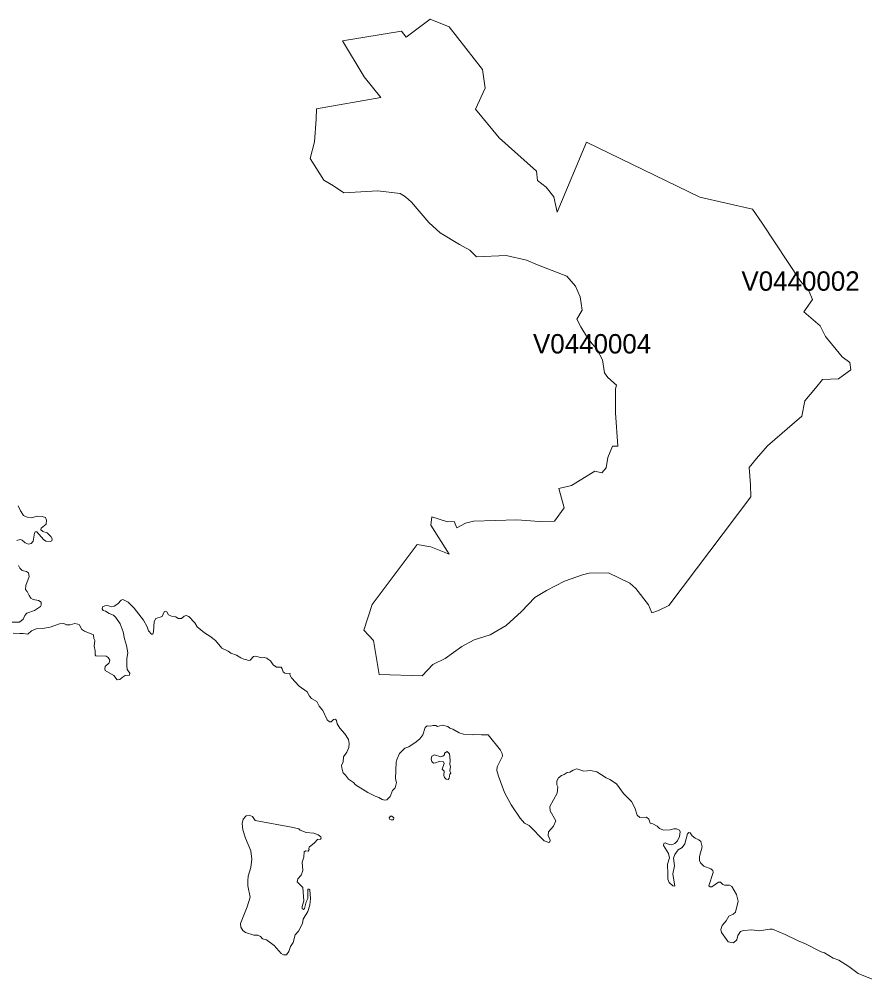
# Model space of a CAD drawing. Extents: x 369010 to 735936, y 6377141 to 6616555.
# Drawn here: x 376246 to 380608, y 6456886 to 6461842 of the extents above; entities that cross this region are included whole.
import ezdxf
from ezdxf.enums import TextEntityAlignment as Align

# ---------------------------------------------------------------- set-up
doc = ezdxf.new("R2010")
doc.units = 0
doc.header["$LTSCALE"] = 40
doc.layers.add('3', color=7, linetype='Continuous', lineweight=13)
doc.layers.add('4', color=7, linetype='Continuous')

msp = doc.modelspace()

# ---------------------------------------------------------------- linework, layer by layer
at = {"layer": '3'}
for points in [[(379071.69, 6460516.27), (378919.43, 6460575.36), (378862.99, 6460598.53), (378757.9, 6460623.52), (378605.63, 6460615.58), (378571.37, 6460649.67), (378517.58, 6460678.63), (378417.78, 6460740.37), (378358.7, 6460792.83), (378269.49, 6460897.93), (378239.21, 6460925.57), (378210.41, 6460942.61), (378096.21, 6460957.18), (377920.28, 6460945.26), (377867.82, 6460982.33), (377816.67, 6461011.3), (377747, 6461123.01), (377768.68, 6461208.91), (377777.78, 6461325.75), (377780.43, 6461379.71), (378111.27, 6461437.47), (378024.88, 6461544.22), (377914.16, 6461730.08), (378218.85, 6461780.06), (378242.35, 6461748.45), (378366.64, 6461841.8), (378463.8, 6461802.41), (378635.75, 6461581.79), (378650.48, 6461486.13), (378599.18, 6461377.23), (378721.32, 6461229.93), (378914.96, 6461057.47), (378920.26, 6461008.81), (378964.94, 6460974.56), (379004.33, 6460926.06), (379021.38, 6460845.79), (379172.98, 6461207.25), (379756.22, 6460924.41), (380029.3, 6460862.51), (380079.11, 6460789.03), (380276.39, 6460490.79), (380319.76, 6460440.97), (380338.13, 6460394.96), (380293.44, 6460331.9), (380377.52, 6460259.58), (380405.16, 6460204.47), (380490.39, 6460099.04), (380531.11, 6460071.4), (380536.4, 6460032.01), (380472.02, 6459986), (380389.27, 6459983.35), (380353.85, 6459937.51), (380298.74, 6459873.13), (380283.01, 6459794.18), (380106.09, 6459640.26), (380049.65, 6459574.56), (380011.59, 6459528.55), (380018.21, 6459439.17), (380020.36, 6459377.77), (379596.5, 6458817.54), (379544.04, 6458791.23), (379509.95, 6458779.48), (379491.57, 6458820.19), (379427.19, 6458904.27), (379395.58, 6458931.91), (379285.36, 6458985.69), (379185.56, 6458984.37), (379151.13, 6458975.93), (379059.11, 6458941.67), (378965.93, 6458894.34), (378905.53, 6458858.92), (378837.34, 6458785.43), (378757.23, 6458714.43), (378675.81, 6458665.77), (378593.22, 6458640.12), (378530.16, 6458606.03), (378443.44, 6458544.29), (378380.38, 6458512.68), (378325.27, 6458453.6), (378102.17, 6458460.22), (378072.87, 6458636.31), (378024.38, 6458688.78), (378066.25, 6458821.51), (378298.13, 6459131.01), (378368.96, 6459119.26), (378463.63, 6459082.35), (378368.96, 6459230.81), (378374.26, 6459274.17), (378455.69, 6459249.18), (378489.78, 6459250.5), (378503.02, 6459217.73), (378547.54, 6459241.4), (378589.58, 6459251.82), (378813.17, 6459259.11), (378930.02, 6459249.84), (379008.14, 6459252.82), (379056.63, 6459321.17), (379030.32, 6459420.97), (379094.7, 6459435.37), (379215.51, 6459510.34)], [(379071.69, 6460516.27), (379115.05, 6460464.97), (379139.88, 6460409.86), (379149.15, 6460340.18), (379122.83, 6460294.17), (379143.52, 6460255.27), (379177.78, 6460197.51), (379201.28, 6460167.23), (379224.95, 6460139.59), (379255.24, 6460084.47), (379264.34, 6460017.45), (379282.71, 6459993.78), (379327.39, 6459954.39), (379322.1, 6459934.69), (379321.44, 6459811.72), (379333.35, 6459638.28), (379305.71, 6459639.6), (379282.38, 6459580.02), (379274.6, 6459527.39), (379250.93, 6459501.07), (379215.51, 6459510.34), (379094.7, 6459435.37), (379030.32, 6459420.97), (379056.63, 6459321.17), (379008.14, 6459252.82), (378930.02, 6459249.84), (378813.17, 6459259.11), (378589.58, 6459251.82), (378547.54, 6459241.4), (378503.02, 6459217.73), (378489.78, 6459250.5), (378455.69, 6459249.18), (378374.26, 6459274.17), (378368.96, 6459230.81), (378463.63, 6459082.35), (378368.96, 6459119.26), (378298.13, 6459131.01), (378066.25, 6458821.51), (378024.38, 6458688.78), (378072.87, 6458636.31), (378102.17, 6458460.22), (378325.27, 6458453.6), (378380.38, 6458512.68), (378443.44, 6458544.29), (378530.16, 6458606.03), (378593.22, 6458640.12), (378675.81, 6458665.77), (378757.23, 6458714.43), (378837.34, 6458785.43), (378905.53, 6458858.92), (378965.93, 6458894.34), (379059.11, 6458941.67), (379151.13, 6458975.93), (379185.56, 6458984.37), (379285.36, 6458985.69), (379395.58, 6458931.91), (379427.19, 6458904.27), (379491.57, 6458820.19), (379509.95, 6458779.48), (379544.04, 6458791.23), (379596.5, 6458817.54), (380020.36, 6459377.77), (380018.21, 6459439.17), (380011.59, 6459528.55), (380049.65, 6459574.56), (380106.09, 6459640.26), (380283.01, 6459794.18), (380298.74, 6459873.13), (380353.85, 6459937.51), (380389.27, 6459983.35), (380472.02, 6459986), (380536.4, 6460032.01), (380531.11, 6460071.4), (380490.39, 6460099.04), (380405.16, 6460204.47), (380377.52, 6460259.58), (380293.44, 6460331.9), (380338.13, 6460394.96), (380319.76, 6460440.97), (380276.39, 6460490.79), (380079.11, 6460789.03), (380029.3, 6460862.51), (379756.22, 6460924.41), (379172.98, 6461207.25), (379021.38, 6460845.79), (379004.33, 6460926.06), (378964.94, 6460974.56), (378920.26, 6461008.81), (378914.96, 6461057.47), (378721.32, 6461229.93), (378599.18, 6461377.23), (378650.48, 6461486.13), (378635.75, 6461581.79), (378463.8, 6461802.41), (378366.64, 6461841.8), (378242.35, 6461748.45), (378218.85, 6461780.06), (377914.16, 6461730.08), (378024.88, 6461544.22), (378111.27, 6461437.47)], [(378111.27, 6461437.47), (377780.43, 6461379.71), (377777.78, 6461325.75), (377768.68, 6461208.91), (377747, 6461123.01), (377816.67, 6461011.3), (377867.82, 6460982.33), (377920.28, 6460945.26), (378096.21, 6460957.18), (378210.41, 6460942.61), (378239.21, 6460925.57), (378269.49, 6460897.93), (378358.7, 6460792.83), (378417.78, 6460740.37), (378517.58, 6460678.63), (378571.37, 6460649.67), (378605.63, 6460615.58), (378757.9, 6460623.52), (378862.99, 6460598.53), (378919.43, 6460575.36), (379071.69, 6460516.27)], [(379215.51, 6459510.34), (379250.93, 6459501.07), (379274.6, 6459527.39), (379282.38, 6459580.02), (379305.71, 6459639.6), (379333.35, 6459638.28), (379321.44, 6459811.72), (379322.1, 6459934.69), (379327.39, 6459954.39), (379282.71, 6459993.78), (379264.34, 6460017.45), (379255.24, 6460084.47), (379224.95, 6460139.59), (379201.28, 6460167.23), (379177.78, 6460197.51), (379143.52, 6460255.27), (379122.83, 6460294.17), (379149.15, 6460340.18), (379139.88, 6460409.86), (379115.05, 6460464.97), (379071.69, 6460516.27)], [(376241.57, 6459331.93), (376252.99, 6459305.78), (376268.72, 6459281.45), (376288.08, 6459273.01), (376310.42, 6459269.2), (376339.39, 6459277.64), (376364.21, 6459275.33), (376381.26, 6459270.53), (376387.88, 6459256.79), (376385.56, 6459235.94), (376359.91, 6459215.41), (376358.42, 6459206.81), (376368.85, 6459199.19), (376390.69, 6459192.08), (376409.23, 6459173.54), (376415.52, 6459160.8), (376415.02, 6459151.2), (376405.42, 6459147.06), (376384.07, 6459149.38), (376371.33, 6459156.99), (376337.57, 6459196.88), (376329.46, 6459197.37), (376324.66, 6459189.26), (376318.53, 6459148.88), (376307.61, 6459136.96), (376294.7, 6459132.66), (376277.16, 6459140.27), (376261.43, 6459153.68), (376251.5, 6459156.99), (376233.46, 6459152.19)], [(376242.73, 6459023.43), (376250.34, 6459008.7), (376262.26, 6458997.78), (376284.6, 6458992.98), (376294.04, 6458984.87), (376297.18, 6458965.83), (376279.64, 6458919.33), (376278.65, 6458899.8), (376288.08, 6458889.87), (376297.18, 6458868.02), (376305.62, 6458854.61), (376317.54, 6458847.99), (376346.17, 6458842.37), (376358.92, 6458833.26), (376359.41, 6458819.03), (376355.61, 6458810.92), (376325.15, 6458791.89), (376285.27, 6458777.16), (376275.34, 6458764.91), (376266.73, 6458746.87), (376247.7, 6458731.15), (376206.82, 6458730.16)], [(376508.53, 6458717.25), (376533.36, 6458723.54), (376548.58, 6458720.72), (376558.02, 6458717.74), (376567.95, 6458694.57), (376583.17, 6458683.98), (376630.34, 6458665.94), (376631.67, 6458646.08), (376636.96, 6458635.98), (376632.66, 6458606.52), (376638.29, 6458583.35), (376637.79, 6458561.84), (376642.09, 6458556.71), (376694.39, 6458554.72), (376704.82, 6458548.6), (376712.93, 6458534.86), (376710.61, 6458520.46), (376689.26, 6458502.42), (376687.77, 6458490.17), (376690.42, 6458481.73), (376735.11, 6458455.58), (376751.49, 6458433.41), (376765.56, 6458434.4), (376777.64, 6458445.49), (376792.2, 6458455.25), (376815.38, 6458458.23), (376817.03, 6458467.34), (376803.96, 6458485.87), (376801.14, 6458505.4), (376801.14, 6458543.8), (376806.27, 6458573.26), (376800.48, 6458610.33), (376789.06, 6458644.09), (376782.77, 6458681.66), (376767.54, 6458722.54), (376745.2, 6458755.31), (376731.96, 6458767.23), (376710.11, 6458775.34), (376691.58, 6458787.09), (376679.17, 6458791.89), (376674.03, 6458799.01), (376675.86, 6458809.43), (376688.76, 6458815.72), (376703.49, 6458816.22), (376721.04, 6458809.93), (376735.77, 6458812.91), (376754.97, 6458826.15), (376771.68, 6458844.19), (376780.29, 6458847), (376808.26, 6458833.76), (376839.21, 6458802.32), (376886.87, 6458741.08), (376906.9, 6458707.32), (376913.52, 6458686.96), (376928.75, 6458669.75), (376935.37, 6458669.25), (376939.67, 6458680.17), (376942.48, 6458734.96), (376951.09, 6458750.18), (376983.86, 6458760.61), (376993.79, 6458783.78), (377000.41, 6458788.08), (377008.02, 6458783.78), (377015.47, 6458768.72), (377031.19, 6458761.93), (377054.86, 6458759.12), (377066.78, 6458750.18), (377083.82, 6458750.18), (377096.73, 6458761.6), (377107.16, 6458765.74), (377120.4, 6458760.61), (377151.51, 6458726.85), (377164.92, 6458707.32), (377202.82, 6458675.54), (377229.96, 6458659.32), (377258.93, 6458636.98), (377292.03, 6458597.09), (377323.31, 6458581.86), (377337.21, 6458570.44), (377366.67, 6458560.02), (377389.01, 6458547.11), (377404.57, 6458539.5), (377415, 6458539), (377429.06, 6458532.87), (377437.17, 6458534.86), (377455.21, 6458554.22), (377467.63, 6458554.72), (377495.6, 6458547.6), (377509.33, 6458548.1), (377523.24, 6458545.78), (377527.54, 6458540.98), (377543.1, 6458531.88), (377556.5, 6458511.03), (377573.38, 6458498.28), (377597.55, 6458498.62), (377603.17, 6458490.67), (377607.48, 6458474.45), (377617.08, 6458467.34), (377644.55, 6458466.34), (377642.73, 6458459.72)], [(376214.93, 6458674.05), (376249.19, 6458671.73), (376266.73, 6458672.56), (376291.39, 6458668.42), (376309.93, 6458685.97), (376333.26, 6458696.89), (376366.03, 6458697.88), (376406.41, 6458705), (376454.41, 6458723.04), (376475.76, 6458723.54), (376490.49, 6458717.25), (376508.53, 6458717.25)], [(377642.73, 6458459.72), (377651.5, 6458443.17), (377689.57, 6458400.14), (377732.1, 6458371.67), (377743.69, 6458348.5), (377753.45, 6458337.41), (377781.59, 6458321.03), (377794, 6458298.19), (377813.2, 6458275.68), (377835.05, 6458226.69), (377846.8, 6458217.26), (377855.57, 6458216.6), (377867.98, 6458229.34), (377876.92, 6458230), (377882.71, 6458224.04), (377887.01, 6458206.5), (377899.43, 6458183.5), (377926.24, 6458154.53), (377944.11, 6458125.07), (377947.42, 6458104.88), (377946.76, 6458085.02), (377936.83, 6458060.86), (377918.79, 6458036.03), (377917.14, 6458010.21), (377909.36, 6457991.18), (377911.51, 6457970.66), (377916.64, 6457954.27), (377929.05, 6457942.19), (377944.77, 6457921.01), (377970.26, 6457904.29), (377981.35, 6457891.05), (378044.74, 6457852.16), (378082.97, 6457832.46), (378101.84, 6457826.01), (378119.22, 6457816.24), (378132.46, 6457812.27), (378141.72, 6457814.59), (378158.94, 6457831.8), (378172.01, 6457862.58), (378185.09, 6457876.65), (378193.03, 6457903.79), (378187.73, 6457922.33), (378190.71, 6458009.22), (378195.18, 6458026.43), (378207.93, 6458053.24), (378235.4, 6458081.38), (378255.26, 6458088.17), (378293.82, 6458113.65), (378312.19, 6458129.71), (378327.42, 6458150.23), (378339.83, 6458187.8), (378350.92, 6458195.91), (378367.31, 6458193.76), (378379.72, 6458197.89), (378395.44, 6458197.23), (378403.55, 6458192.43), (378428.38, 6458199.22), (378456.51, 6458193.43), (378468.26, 6458184.82), (378483.16, 6458179.69), (378516.26, 6458159.83), (378538.77, 6458153.87), (378584.45, 6458149.57), (378594.54, 6458151.22), (378630.13, 6458150.23), (378664.72, 6458148.91), (378728.77, 6458069.96), (378738.2, 6458052.58), (378739.52, 6458038.85), (378711.39, 6457984.39), (378710.4, 6457965.03), (378719, 6457935.74), (378749.29, 6457851.83), (378783.88, 6457788.11), (378829.39, 6457719.92), (378852.56, 6457694.1), (378876.4, 6457681.69), (378953.36, 6457603.24), (378978.18, 6457593.47), (378983.81, 6457596.78), (378984.47, 6457606.22), (378975.04, 6457630.05), (378976.03, 6457648.42), (379002.01, 6457679.04), (379013.43, 6457706.18), (378985.79, 6457758.32), (378982.82, 6457780.66), (379021.38, 6457849.18), (379024.03, 6457881.45), (379019.39, 6457892.21), (379018.73, 6457912.9), (379027.5, 6457927.96), (379043.22, 6457939.38), (379056.3, 6457944.18), (379072.85, 6457954.6), (379086.92, 6457956.92), (379104.3, 6457967.35), (379123.16, 6457973.97), (379159.41, 6457962.55), (379193.67, 6457964.87)], [(379193.67, 6457964.87), (379225.11, 6457958.25), (379274.6, 6457927.3), (379293.47, 6457918.69), (379326.57, 6457896.84), (379362.48, 6457846.2), (379403.86, 6457804.82), (379420.9, 6457772.72), (379434.31, 6457735.81), (379448.21, 6457723.06), (379482.64, 6457724.06), (379493.73, 6457714.62), (379501.51, 6457694.43), (379515.24, 6457689.8), (379537.09, 6457679.04), (379548.84, 6457666.63), (379568.7, 6457657.52), (379603.29, 6457659.84), (379622.99, 6457665.3), (379635.73, 6457664.97), (379652.61, 6457658.52), (379655.92, 6457648.75), (379651.95, 6457624.26), (379641.52, 6457602.91), (379628.45, 6457589.17), (379609.91, 6457582.05), (379599.15, 6457583.05), (379577.64, 6457592.48), (379570.69, 6457589.01), (379570.02, 6457578.08), (379595.84, 6457538.03), (379599.81, 6457514.53), (379589.72, 6457482.09), (379592.53, 6457430.29), (379591.87, 6457404.47), (379599.48, 6457387.75), (379617.19, 6457370.71), (379628.12, 6457368.55), (379618.19, 6457431.78), (379625.47, 6457473.65), (379621.83, 6457513.87), (379628.45, 6457532.73), (379645, 6457555.9), (379665.52, 6457568.32), (379679.92, 6457586.69), (379692.66, 6457639.15), (379700.28, 6457645.44), (379706.4, 6457644.45), (379717.16, 6457628.06), (379732.22, 6457616.64), (379751.75, 6457608.54), (379762.17, 6457598.77), (379768.3, 6457572.29), (379754.89, 6457521.65), (379754.89, 6457501.78), (379760.68, 6457488.38), (379777.07, 6457471.66), (379813.65, 6457458.59), (379823.41, 6457450.15), (379825.4, 6457440.05), (379803.88, 6457370.87), (379809.51, 6457364.91), (379818.28, 6457364.91), (379853.2, 6457389.41), (379863.63, 6457389.41), (379875.05, 6457376.66), (379884.81, 6457373.68), (379909.64, 6457373.68), (379921.72, 6457366.24), (379946.21, 6457325.36), (379954.82, 6457290.77), (379940.42, 6457234.33), (379929, 6457224.57), (379906.99, 6457213.97), (379893.42, 6457189.15), (379872.73, 6457166.31), (379865.28, 6457145.45), (379868.59, 6457129.07), (379902.19, 6457082.07), (379930.33, 6457077.27), (379948.2, 6457091.5), (379953.5, 6457114.51), (379966.24, 6457134.37), (379981.47, 6457140.49), (380024.99, 6457143.14), (380062.23, 6457137.68), (380118.34, 6457147.44), (380131.41, 6457147.44), (380197.28, 6457119.31), (380267.95, 6457084.71), (380298.24, 6457073.63), (380382.81, 6457029.77), (380399.86, 6457024.97), (380444.88, 6456997.83), (380473.51, 6456987.07), (380526.14, 6456955.13), (380573.81, 6456918.22), (380653.58, 6456885.78)]]:
    msp.add_lwpolyline(points, dxfattribs=at)
for points in [[(378453.37, 6458063.67), (378439.63, 6458054.9), (378439.3, 6458046.13), (378431.52, 6458039.18), (378421.76, 6458036.86), (378388.82, 6458047.12), (378373.76, 6458040.17), (378370.78, 6458024.78), (378375.42, 6458012.7), (378383.86, 6458004.26), (378393.62, 6458004.59), (378412.99, 6458012.03), (378434.83, 6458011.04), (378438.31, 6458001.94), (378427.22, 6457971.65), (378438.14, 6457961.56), (378436.49, 6457939.54), (378439.3, 6457928.79), (378449.23, 6457921.01), (378459.33, 6457920.01), (378464.46, 6457925.81), (378467.77, 6457946.83), (378473.06, 6457951.29), (378467.44, 6457963.71), (378470.42, 6457986.05), (378466.77, 6457997.14), (378469.09, 6458018.65), (378465.78, 6458051.92)], [(377610.13, 6457014.71), (377624.52, 6457015.04), (377636.28, 6457032.08), (377646.21, 6457056.91), (377659.94, 6457077.76), (377670.37, 6457118.31), (377686.59, 6457136.19), (377708.1, 6457176.4), (377711.41, 6457198.91), (377734.92, 6457238.8), (377745.18, 6457270.74), (377749.15, 6457304.5), (377744.85, 6457349.52), (377740.21, 6457353.82), (377735.74, 6457352.83), (377735.08, 6457304.84), (377725.98, 6457287.46), (377717.37, 6457253.53), (377712.57, 6457247.9), (377706.61, 6457252.2), (377706.28, 6457263.96), (377714.23, 6457292.75), (377708.77, 6457362.6), (377680.63, 6457391.23), (377684.27, 6457406.29), (377700.33, 6457425.65), (377709.92, 6457449.15), (377706.28, 6457492.52), (377713.9, 6457517.67), (377716.05, 6457546.47), (377724.65, 6457550.28), (377735.91, 6457549.28), (377742.03, 6457557.89), (377739.55, 6457563.02), (377741.37, 6457569.97), (377769.84, 6457592.81), (377784.24, 6457609.53), (377800.79, 6457611.68), (377804.1, 6457615.98), (377802.44, 6457623.43), (377789.04, 6457633.69), (377765.2, 6457642.79), (377726.47, 6457646.44), (377695.53, 6457657.86), (377687.75, 6457664.31), (377650.84, 6457673.41), (377464.15, 6457706.84), (377450.08, 6457728.69), (377432.37, 6457735.48), (377416.82, 6457731.67), (377400.6, 6457714.62), (377395.63, 6457691.78), (377400.27, 6457658.85), (377413.67, 6457615.65), (377440.15, 6457551.93), (377446.94, 6457508.9), (377441.31, 6457465.37), (377427.24, 6457419.7), (377425.09, 6457395.86), (377426.08, 6457369.71), (377437.5, 6457312.28), (377422.44, 6457262.96), (377388.52, 6457175.74), (377390.17, 6457156.87), (377399.27, 6457140.82), (377414.33, 6457129.4), (377456.21, 6457116.66), (377477.06, 6457115.66), (377490.47, 6457109.87), (377501.55, 6457097.13), (377522.24, 6457092.16), (377560.81, 6457063.36), (377597.71, 6457020.66)], [(378164.56, 6457710.65), (378176.81, 6457711.48), (378177.8, 6457721.91), (378168.7, 6457729.68), (378161.25, 6457730.35), (378154.14, 6457721.24), (378156.12, 6457713.8)]]:
    msp.add_lwpolyline(points, close=True, dxfattribs=at)

# ---------------------------------------------------------------- texts
at = {"layer": '4'}
for s, p in [('V0440002', (380276.4, 6460440.79)), ('V0440004', (379201.28, 6460117.22))]:
    msp.add_text(s, height=100, dxfattribs=at).set_placement(p, align=Align.CENTER)

doc.saveas('drawing.dxf')
